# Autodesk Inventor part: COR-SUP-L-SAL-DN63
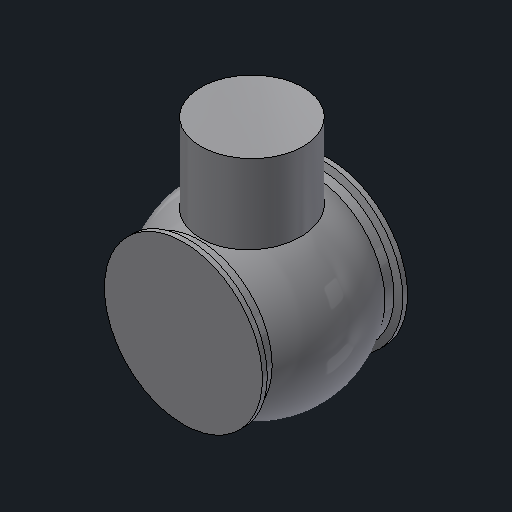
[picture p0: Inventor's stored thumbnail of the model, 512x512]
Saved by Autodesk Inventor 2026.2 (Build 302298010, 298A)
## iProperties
Created: 2026-03
Part Number: COR-SUP-L-SAL-DN63
Material: Generico
Document SubType Name: Modeling
Designer: marz-m
Density: 1 g/cm^3
Appearance: Default
Author: marz-m
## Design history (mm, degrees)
feature "Solido1"
node "Solido2"
